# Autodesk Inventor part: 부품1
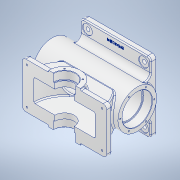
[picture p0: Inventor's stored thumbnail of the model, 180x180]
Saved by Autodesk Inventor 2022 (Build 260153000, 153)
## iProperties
Created: 2023-07
Part Number: 부품1
Material: 알루미늄 6061
Document SubType Name: Modeling
Designer: PC-13
Mass: 5726.59 g
Surface Area: 2841.54 cm^2
Volume: 2120.96 cm^3
Density: 2.7 g/cm^3
Appearance: 알루미늄 - 평지
Author: PC-13
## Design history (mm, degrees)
sketch "스케치1"
  geometry: L1 (-100, 100)-(100, 100); L2 (100, 100)-(100, -100); L3 (100, -100)-(-100, -100); L4 (-100, -100)-(-100, 100); L5 (-100, 100)-(100, -100); L6 (100, 100)-(-100, -100); 1 further point
  constraints: 12 end point, 2 midpoint, 2 parallel, 1 horizontal, 1 perpendicular
  dimensions: "d0" = 200 distance of L1.start L1.end; "d1" = 200 distance of L3.end L1.start
extrude "돌출1" new body sketch "스케치1" distance "d2" = 15; taper "d3" = 0 deg
fillet "모깎기1" dims "d4" = 10
sketch "스케치2"
  geometry: L1 (114.447, 60)-(-118.109, 60); L2 (-90, 0)-(90, 0) reference; L3 (0, -19.902)-(0, 119.411) reference; C1 r 55 at (0, 60); 1 further point
  constraints: 2 end point, 2 point on line, 1 centre point, 1 horizontal
  dimensions: "d5" = 60 distance between parallel lines of L2 L1; "d6" = 110 diameter of C1
extrude "돌출2" join sketch "스케치2" distance "d7" = 107; taper "d9" = 0 deg; dims "d8" = 135, "d10" = 0
node "작업 평면1"
sketch "스케치3"
  geometry: L1 (-120, -65)-(120, -65); L2 (120, -65)-(120, 65); L3 (120, 65)-(-120, 65); L4 (-120, 65)-(-120, -65); L5 (-120, -65)-(120, 65); L6 (120, -65)-(-120, 65); 1 further point
  constraints: 12 end point, 2 midpoint, 2 parallel, 1 horizontal, 1 perpendicular
  dimensions: "d12" = 240 distance of L1.start L1.end; "d13" = 130 distance of L3.end L1.start
extrude "돌출3" join sketch "스케치3" distance "d14" = 15; taper "d15" = 0 deg
sketch "스케치4"
  geometry: L1 (0, -50.745)-(0, 304.467) reference; L2 (-120, 160)-(120, 160) reference; L3 (120, 160)-(-120, 160) reference; A1 r 45 centre (0, 160) between (-45, 160) and (45, 160); 1 further point
  constraints: 3 point on line, 2 point on circle, 1 centre point, 1 midpoint
  dimensions: "d16" = 90 diameter of A1
extrude "돌출4" join sketch "스케치4" stored distance "d17" = 140; taper "d18" = 0 deg
sketch "스케치5"
  geometry: L1 (-120, 160)-(120, 160) reference; L2 (-120, 160)-(120, 160) reference; L3 (-45, 160)-(45, 160); A1 r 45 centre (0, 160) between (-45, 160) and (45, 160) reference; A2 r 100 centre (0, 160) between (-100, 160) and (100, 160); 1 further point
  constraints: 2 end point, 2 point on circle, 2 point on line, 1 centre point, 1 coincident, 1 horizontal
  dimensions: "d19" = 200 diameter of A2
extrude "돌출5" join sketch "스케치5" stored distance "d20" = 90; taper "d21" = 0 deg
sketch "스케치6"
  geometry: L1 (-154.268, 60)-(175.196, 60); L2 (90, 0)-(-90, 0) reference; L3 (-107, 60)-(-82, 60); L4 (-82, 60)-(-82, 102.5); L5 (-82, 102.5)-(-107, 102.5); L6 (-107, 102.5)-(-107, 60); L7 (-82, 60)-(110, 60); L8 (110, 60)-(110, 98.5); L9 (110, 98.5)-(-82, 98.5); L10 (-82, 98.5)-(-82, 60); L11 (110, 60)-(135, 60); L12 (135, 60)-(135, 102.5); L13 (135, 102.5)-(110, 102.5); L14 (110, 102.5)-(110, 60); L15 (135, 5)-(135, 115) reference; L16 (-107, 115)-(-107, 5) reference; 6 further points
  constraints: 26 end point, 6 parallel, 4 horizontal, 3 perpendicular, 2 midpoint, 2 point on line
  dimensions: "d22" = 60 distance between parallel lines of L2 L1; "d23" = 85 diameter of L13 L1; "d24" = 85 diameter of L5 L1; "d25" = 77 diameter of L9 L1; "d26" = 25 distance of L12.end L13.end; "d27" = 25 distance of L4.end L5.end
revolve "회전1" sketch "스케치6" stored, may be unused: angle "d28" = 90 deg
sketch "스케치7"
  geometry: L1 (0, -73.395)-(0, 440.372) reference; L2 (45, 160)-(-45, 160) reference; L3 (120, 160)-(45, 160) reference; L4 (-45, 160)-(-120, 160) reference; A1 r 87 centre (0, 160) between (-87, 160) and (87, 160); 1 further point
  constraints: 2 point on circle, 2 point on line, 1 centre point, 1 midpoint
  dimensions: "d29" = 174 diameter of A1
extrude "돌출6" cut sketch "스케치7" stored distance "d30" = 64; taper "d31" = 0 deg
sketch "스케치8"
  geometry: L1 (-65, 160)-(65, 160) reference; L2 (-70, 160)-(-65, 160) reference; L3 (65, 160)-(70, 160) reference; L4 (-70, 160)-(-47, 160); L5 (-47, 160)-(-47, 191); L6 (-47, 191)-(-70, 191); L7 (-70, 191)-(-70, 160); L8 (-47, 160)-(47, 160); L9 (47, 160)-(47, 187.5); L10 (47, 187.5)-(-47, 187.5); L11 (-47, 187.5)-(-47, 160); L12 (47, 160)-(70, 160); L13 (70, 160)-(70, 191); L14 (70, 191)-(47, 191); L15 (47, 191)-(47, 160); 3 further points
  constraints: 24 end point, 6 parallel, 3 horizontal, 3 perpendicular, 1 point on line
  dimensions: "d32" = 62 diameter of L6 L1; "d33" = 55 diameter of L10 L1; "d34" = 23 distance of L5.end L6.end; "d35" = 23 distance of L13.end L14.end
revolve "회전2" sketch "스케치8" stored, may be unused: angle "d36" = 90 deg
sketch "스케치9" dims "d37" = 74
  geometry: L1 (0, 160)-(-43.74, 116.26); L2 (0, -39.4)-(0, 236.4) reference; A1 r 31 centre (0, 160) between (-31, 160) and (31, 160) reference; 3 further points
  constraints: 2 end point, 1 coincident, 1 point on line, 3 other
  dimensions: "d38" = 45 deg angle of L1 L2
hole "구멍1" sketch "스케치9" at (-26.163, 133.837) diameter "d39" = 4.134; stored, may be unused: countersink angle "d43" = 90 deg, drill point angle "d45" = 118 deg; dims "d40" = 10, "d41" = 4, "d42" = 2, "d44" = 12
sketch "스케치10" dims "d46" = 97
  geometry: L1 (92, 0)-(-132, 0) reference; C1 r 42.5 at (0, 0) reference; C2 r 55 at (0, 0) reference; 3 further points
  constraints: 1 coincident, 1 horizontal alignment, 1 point on line, 2 other
hole "구멍2" sketch "스케치10" at (-48.5, 0) diameter "d47" = 4.134; stored, may be unused: countersink angle "d51" = 90 deg, drill point angle "d53" = 118 deg; dims "d48" = 10, "d49" = 4, "d50" = 2, "d52" = 12
sketch "스케치11" dims "d57" = 97
  geometry: L1 (-92, 0)-(132, 0) reference; C1 r 55 at (0, 0) reference; 3 further points
  constraints: 1 coincident, 1 horizontal alignment, 1 point on line, 2 other
hole "구멍3" sketch "스케치11" at (48.5, 0) diameter "d58" = 4.134; stored, may be unused: countersink angle "d62" = 90 deg, drill point angle "d64" = 118 deg; dims "d59" = 10, "d60" = 4, "d61" = 2, "d63" = 12
sketch "스케치12"
  geometry: L1 (-196.358, 0)-(233.151, 0) reference; L2 (0, -140)-(0, 140) reference; 5 further points
  constraints: 4 symmetric about line, 2 vertical alignment, 1 horizontal alignment
  dimensions: "d68" = 160 distance of point (-80, 80) point (80, 80); "d69" = 160 distance of point (80, -80) point (80, 80)
hole "구멍4" sketch "스케치12" at (80, 80), (-80, -80), (-80, 80), (80, -80) diameter "d70" = 28; stored, may be unused: countersink angle "d74" = 90 deg, drill point angle "d76" = 0 deg; dims "d71" = 10, "d72" = 4, "d73" = 2, "d75" = 2
sketch "스케치13"
  geometry: C1 r 14 at (160, 0) reference; C2 r 14 at (160, 160) reference; C3 r 14 at (0, 160) reference; C4 r 14 at (0, 0) reference; 5 further points
  constraints: 4 coincident
hole "구멍5" sketch "스케치13" at (0, 0), (160, 0), (160, 160), (0, 160) diameter "d77" = 11; stored, may be unused: countersink angle "d81" = 90 deg, drill point angle "d83" = 0 deg; dims "d78" = 6, "d79" = 4, "d80" = 2, "d82" = 13
sketch "스케치14"
  geometry: L1 (-267.861, 0)-(232, 0) reference; L2 (0, -169.083)-(0, 147.879) reference; 5 further points
  constraints: 4 symmetric about line
  dimensions: "d84" = 214 distance of point (-107, -52) point (107, -52); "d85" = 104 distance of point (107, 52) point (107, -52)
hole "구멍6" sketch "스케치14" at (107, -52), (107, 52), (-107, 52), (-107, -52) diameter "d86" = 4.917; stored, may be unused: countersink angle "d90" = 90 deg, drill point angle "d92" = 0 deg; dims "d87" = 15, "d88" = 4, "d89" = 2, "d91" = 17.1
sketch "스케치15"
  geometry: L1 (90, 100)-(-90, 100) reference; L2 (0, -140)-(0, 140) reference; 2 further points
  constraints: 1 point on line, 1 other
  dimensions: "d93" = 15 distance from line of L1 point (0, 85)
feature "엠보싱1" sketch "스케치15" dims "d94" = 0.5, "d95" = 0
fillet "모깎기2" dims "d96" = 15
fillet "모깎기3" dims "d97" = 1.1
chamfer "모따기1" distance "d98" = 1; stored, may be unused: second distance "d99" = 2, angle "d100" = 45 deg
fillet "모깎기4" dims "d101" = 10
fillet "모깎기5" dims "d102" = 1
fillet "모깎기6" dims "d103" = 3
fillet "모깎기7" dims "d104" = 3
fillet "모깎기8" dims "d105" = 3
fillet "모깎기9" dims "d106" = 3
chamfer "모따기2" distance "d107" = 1; stored, may be unused: second distance "d108" = 2, angle "d109" = 45 deg
node "솔리드1"
mirror "미러1"
mirror "미러2"
pattern_circular "원형 패턴1" dims angle "d55" = 360 deg
pattern_circular "원형 패턴2" dims angle "d66" = 360 deg
node "투영된 루프1"
feature "A9D066F2-1C7D-4E18-AEED-F7BC21143FA4" dims "d70" = 28, "d71" = 10, "d72" = 4, "d73" = 2, "d74" = 90 deg, "d75" = 2, "d76" = 0
